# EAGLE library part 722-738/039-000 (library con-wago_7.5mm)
Serie 722, Federleiste mit Verriegelungsklinken / Series 722, Female connector with locking levers Polzahl / Pole No.: 8 Bemessungsspannung / Rated Voltage: 400 V Nennstrom / Nominal Current: 12 A Farbe / Color: xxxx / xxxx Stand: 01.01.2012. Die jeweils aktuellen Daten zu diesem Artikel finden Sie in unserem Produktkatalog, den Sie unter www.wago.com einsehen können. As of: 01/01/2012. Please find the newest data for this article in our product catalogue, which can be viewed under www.wago.com.
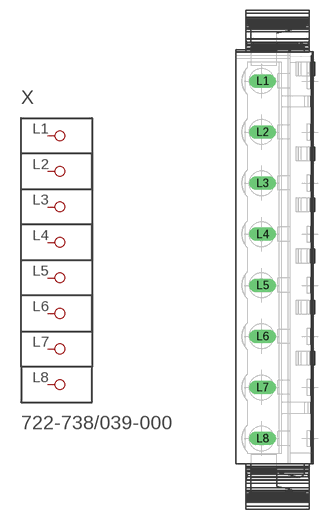
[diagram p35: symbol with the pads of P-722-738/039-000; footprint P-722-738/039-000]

Designator prefix X

## 722-738/039-000  [P-722-738/039-000]
L1  P1
L2  P2
L3  P3
L4  P4
L5  P5
L6  P6
L7  P7
L8  P8

## Footprint P-722-738/039-000 (pad centres in mm)
drill 1.3 long: L1 -2.122,26.25; L2 -2.122,18.75; L3 -2.122,11.25; L4 -2.122,3.75; L5 -2.122,-3.75; L6 -2.122,-11.25; L7 -2.122,-18.75; L8 -2.122,-26.25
